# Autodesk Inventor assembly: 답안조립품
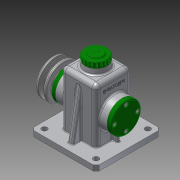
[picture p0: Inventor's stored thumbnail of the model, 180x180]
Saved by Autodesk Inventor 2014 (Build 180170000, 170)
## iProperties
Created: 2017-08
Part Number: 답안조립품
Document SubType Name: Assembly
Designer: user
Author: user
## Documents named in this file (14)
- E:\470825V1010\답안조립품.iam
- E:\470825V1010\본체.ipt
- E:\470825V1010\베어링 15 x 35 x 11.ipt
- E:\470825V1010\뒤커버.ipt
- E:\470825V1010\앞커버.ipt
- E:\470825V1010\축.ipt
- E:\470825V1010\키 5 x 5 x 14.ipt
- E:\470825V1010\멈춤링 15 x 1.ipt
- E:\470825V1010\볼트 M4 x 10.ipt
- E:\470825V1010\오일실 15 25 7.ipt
- E:\470825V1010\V-벨트풀리.ipt
- E:\470825V1010\와셔.ipt
- E:\470825V1010\볼트 M6 x 12.ipt
- E:\470825V1010\상부캡.ipt
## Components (1 placed, 1 different names)
1. V-벨트풀리:1 — 각도:2
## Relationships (1: Angle 1)
- 각도:2 [Angle]: V-벨트풀리:1
